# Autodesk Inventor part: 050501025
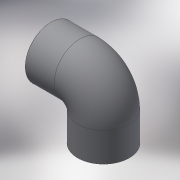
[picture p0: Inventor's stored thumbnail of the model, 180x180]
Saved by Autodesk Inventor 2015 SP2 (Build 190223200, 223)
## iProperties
Created: 2017-10
Part Number: 050501025
Material: Generic
Description: PLASSON THREADED 90° ELBOW PVC 2.1/2"
Document SubType Name: Modeling
Designer: KIM
Density: 1 g/cm^3
Appearance: Default
Author: KIM
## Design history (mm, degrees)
derived "050501.ipt"
feature "Solid1::050501.ipt"
tag "TaggingFeature1"
body "Solid1"
other parameters: "d7" = 0.72226, "d10" = 85, "d13" = 90 deg, "d19" = 90 deg, "d20" = 72.226, "d21" = 29, "d22" = 0, "d24" = 90 deg, "d26" = 65.0034, "d27" = 90 deg, "d28" = 29, "G_" = 72.226, "lt_" = 29
